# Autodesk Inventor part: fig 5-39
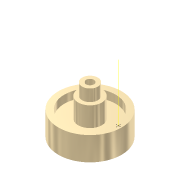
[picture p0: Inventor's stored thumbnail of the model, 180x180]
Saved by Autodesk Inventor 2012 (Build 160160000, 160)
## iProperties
Shininess: 65.0
Length Units: 11269
Angle Units: 11279
Time Units: 11290
Mass Units: 11283
Length Display Precision: 3
Angle Display Precision: 2
Created: 2001-11
Part Number: fig 5-39
Document SubType Name: Modeling
Designer: Renu Muthoo
Density: 1 g/cm^3
Material: Default
Density: 0.0
Volumn: 0.0
Area: 0.0
PropertySet Name: Model Information
Control State: 0
Master: False
Checked Out: False
Author: Renu Muthoo
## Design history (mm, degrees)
sketch "Sketch1"
  geometry: L1 (2.694, 30.112)-(5.194, 30.112); L2 (5.194, 30.112)-(5.194, 22.612); L3 (5.194, 22.612)-(7.694, 22.612); L4 (7.694, 22.612)-(7.694, 10.112); L5 (7.694, 10.112)-(16.444, 10.112); L6 (16.444, 10.112)-(16.444, 15.112); L7 (16.444, 15.112)-(20.194, 15.112); L8 (0.194, -4.034)-(0.194, 25.966); L9 (2.694, 30.112)-(2.694, 0.112); L10 (2.694, 0.112)-(20.194, 0.112); L11 (20.194, 0.112)-(20.194, 15.112)
  constraints: 22 end point, 7 parallel, 2 perpendicular, 1 horizontal
  dimensions: "d0" = 5 diameter of L9 L8; "d1" = 10 diameter of L2 L8; "d2" = 15 diameter of L4 L8; "d3" = 32.5 diameter of L6 L8; "d4" = 40 diameter of L11 L8; "d5" = 15 distance of L10.end L7.end; "d6" = 22.5 distance between parallel lines of L3 L10; "d7" = 30 distance between parallel lines of L1 L10; "d8" = 10 distance between parallel lines of L10 L5
revolve "Revolution1" sketch "Sketch1" stored, may be unused: angle "d9" = 90 deg
workaxis "Work Axis1"
sketch "Sketch2"
  geometry: 1 further point
node "Sketch3"
workaxis "Work Axis3"
body "Solid1"
